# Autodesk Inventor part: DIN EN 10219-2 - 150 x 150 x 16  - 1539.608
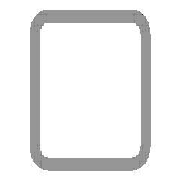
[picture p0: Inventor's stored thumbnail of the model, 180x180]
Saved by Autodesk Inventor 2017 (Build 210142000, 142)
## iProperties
Created: 2017-11
Part Number: DIN EN 10219-2 - 150 x 150 x 16  - 1539.608
Material: Steel, Mild
Description: Cold formed welded structural hollow sections of non-alloy and fine grain structural steel
Document SubType Name: Modeling
Standard: DIN
Designer: iusti
Standard Revision: 2006-07
Standards Organization: DIN
Language: en-US
Size Designation: 150 x 150 x 16
Categories: <MemberInstance><Categories><Category DisplayName="Structural Shapes" InternalName="089c4875-fa83-4c05-b084-43b9cc11f5ed" Mnemonic="GRDR"><CategoryParameter Dis
Stock Number: 150 x 150 x 16
Mass: 90369.3 g
Surface Area: 14539.6 cm^2
Volume: 11512 cm^3
Density: 7.85 g/cm^3
Appearance: Semi-Polished
IsCustomPart: 1
G_W: 150.000 mm
G_H: 150.000 mm
G_L: 1539.608 mm
+B4BE7288-8744-4333-8402-F61C489DE7FB+CUTDETAIL2: Cut
_CCFamilyMember: 76
_CCFamilyDisplayName: DIN EN 10219-2 (Square Hollow Section - Cold Formed) - Cold formed welded structural hollow sections of non-alloy and fine grain structural steel
_FrameMemberDoc: Frame Member File
_Version: 15.0.0
_GetPNFromCC: 1
Author: iusti
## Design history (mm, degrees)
node "Start plane"
node "End plane"
sketch "Sketch"
  geometry: L1 (-75, -27)-(-75, 27); L2 (-27, 75)-(27, 75); L3 (75, 27)-(75, -27); L4 (27, -75)-(-27, -75); L5 (-27, 59)-(27, 59); L6 (59, 27)-(59, -27); L7 (27, -59)-(-27, -59); L8 (-59, -27)-(-59, 27); L9 (0, 118.918)-(0, -118.918) reference; L10 (-118.918, 0)-(118.918, 0) reference; A1 r 48 centre (-27, -27) between (-75, -27) and (-27, -75); A2 r 48 centre (-27, 27) between (-27, 75) and (-75, 27); A3 r 48 centre (27, 27) between (75, 27) and (27, 75); A4 r 48 centre (27, -27) between (27, -75) and (75, -27); A5 r 32 centre (-27, 27) between (-27, 59) and (-59, 27); A6 r 32 centre (27, 27) between (59, 27) and (27, 59); A7 r 32 centre (27, -27) between (27, -59) and (59, -27); A8 r 32 centre (-27, -27) between (-59, -27) and (-27, -59)
  constraints: 16 end point, 16 point on circle, 8 centre point, 8 tangent, 4 parallel, 3 equal radius, 2 perpendicular, 7 other
  dimensions: "d7" = 48 radius of A1 (= G_IR); "d10" = 150 distance between parallel lines of L2 L4 (= G_H); "d11" = 150 distance between parallel lines of L1 L3 (= G_W); "d12" = 16 distance between parallel lines of L3 L6 (= G_T); "d15" = 75 distance between parallel lines of L2 L10 (= 0.5 x d10); "d16" = 75 distance between parallel lines of L9 L3 (= 0.5 x d11)
extrude "Body" new body sketch "Sketch" stored distance "d3" = 1539.60835 (= G_L); taper "d4" = 0 deg
node "Driven Length"
  sketch "Sketch3"
    geometry: L1 (0, 0)-(10, 0) reference
    constraints: 2 end point, 1 horizontal
  workplane "Work Plane3"
  sketch "Sketch4"
    geometry: L1 (-2, 75)-(12, 75) reference; L2 (-2, 1614.608)-(12, 1614.608) reference
    dimensions: "d18" = 1539.60835 distance between parallel lines of L1 L2 (derived)
workplane "Work Plane5"
split "Split2"
body "Solid1"
other parameters: "G_W" = 150 [user parameter; used in 1 equation term], "G_H" = 150 [user parameter; used in 1 equation term], "G_T" = 16 [user parameter; used in 1 equation term], "G_IR" = 48 [user parameter; used in 1 equation term], "G_L" = 1539.60835 (= d18) [user parameter; used in 1 equation term], "G_OFFSET_START" = -75 [user parameter; used in 1 equation term], "G_OFFSET_END" = 0 [user parameter; used in 1 equation term], "d13" = 75 (= -G_OFFSET_START), "d14" = 1614.60835 (= G_OFFSET_END + B_L), "B_L" = 1614.60835 [user parameter; used in 1 equation term], "d17" = 90 deg
